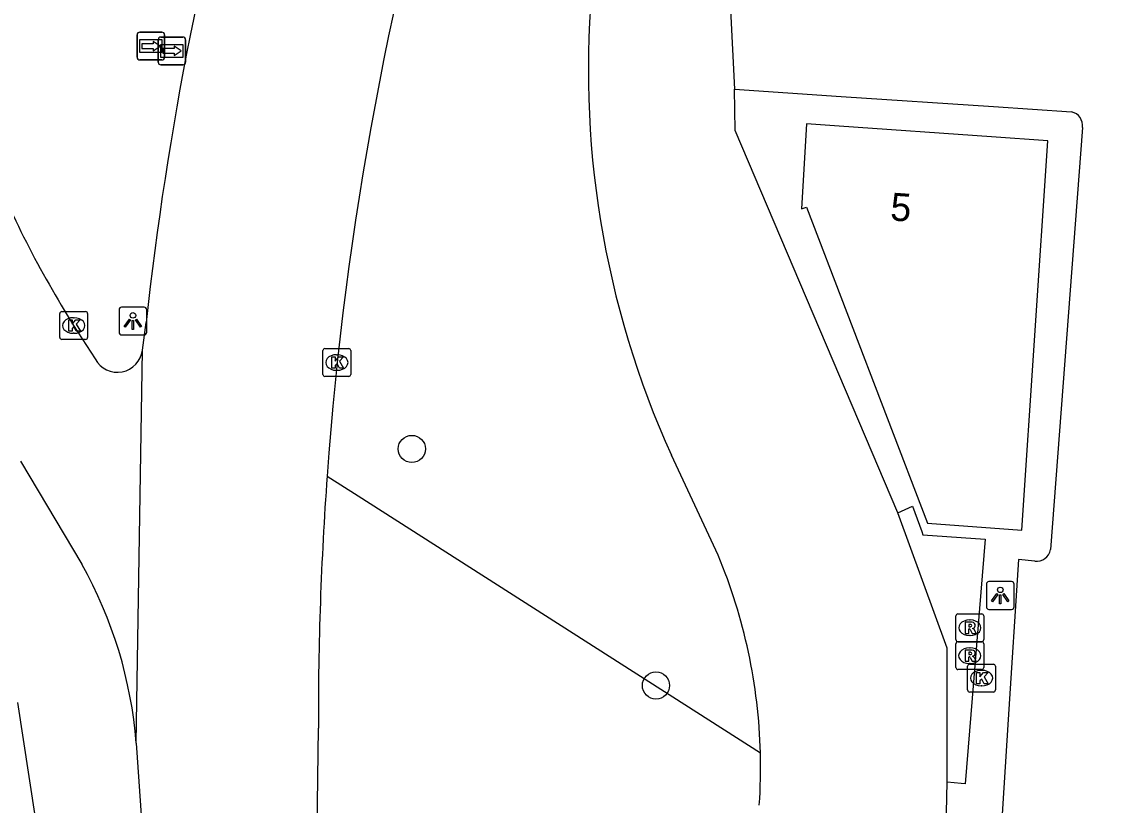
# Model space of a CAD drawing. Extents: x 161084 to 161928, y 385355 to 386522.
# Drawn here: x 161798.81 to 161838.18, y 385406.42 to 385434.56 of the extents above; entities that cross this region are included whole.
import ezdxf

# ---------------------------------------------------------------- set-up
doc = ezdxf.new("R2010")
doc.units = 0
for name, color, linetype in [('IMGEO_Berm_groen', 7, 'Continuous'), ('IMGEO_Boom', 7, 'Continuous'), ('IMGEO_Fietspad_open', 7, 'Continuous'), ('IMGEO_Kolk', 7, 'Continuous'), ('IMGEO_Lichtpunt', 7, 'Continuous'), ('IMGEO_Pand', 7, 'Continuous'), ('IMGEO_Pand_nummerreeks', 7, 'Continuous'), ('IMGEO_Rijbaan_lokaal_gesloten', 7, 'Continuous'), ('IMGEO_Rijbaan_lokaal_open', 7, 'Continuous'), ('IMGEO_Rijbaan_regionaal_gesloten', 7, 'Continuous'), ('IMGEO_Rioolput', 7, 'Continuous'), ('IMGEO_Voetpad_open', 7, 'Continuous'), ('IMGEO_Wegwijzer', 7, 'Continuous')]:
    doc.layers.add(name, color=color, linetype=linetype)

msp = doc.modelspace()

# ---------------------------------------------------------------- linework, layer by layer
at = {"layer": 'IMGEO_Berm_groen'}
for points in [[(161823.838, 385415.395), (161822.158, 385418.993)], [(161809.783, 385418.239), (161810.901, 385417.525), (161825.361, 385408.299)]]:
    msp.add_lwpolyline(points, dxfattribs=at)
for centre, radius, start, end in [((161852.618, 385432.799), 33.443, 174.1577, 204.3823), ((161805.665, 385407.783), 19.702, 1.5001, 22.7269), ((161805.737, 385407.787), 19.63, 356.0062, 1.4938)]:
    msp.add_arc(centre, radius, start, end, dxfattribs=at)
at = {"layer": 'IMGEO_Boom'}
for centre in [(161812.829, 385419.214), (161821.605, 385410.717)]:
    msp.add_circle(centre, 0.489, dxfattribs=at)
at = {"layer": 'IMGEO_Fietspad_open'}
msp.add_lwpolyline([(161798.655, 385410.11), (161800.123, 385400.485), (161800.172, 385400.245)], dxfattribs=at)
at = {"layer": 'IMGEO_Kolk'}
for p, q in [((161800.173, 385423.223), (161800.173, 385424.075)), ((161800.248, 385424.149), (161801.1, 385424.149)), ((161801.174, 385424.075), (161801.174, 385423.223)), ((161800.661, 385423.929), (161800.686, 385423.929)), ((161800.684, 385423.369), (161800.659, 385423.369)), ((161801.1, 385423.149), (161800.248, 385423.149)), ((161809.707, 385422.82), (161810.559, 385422.82)), ((161809.632, 385421.894), (161809.632, 385422.746)), ((161810.12, 385422.6), (161810.145, 385422.6)), ((161810.633, 385422.746), (161810.633, 385421.894)), ((161810.143, 385422.04), (161810.118, 385422.04)), ((161810.559, 385421.82), (161809.707, 385421.82)), ((161832.808, 385410.555), (161832.808, 385411.407)), ((161832.883, 385411.481), (161833.735, 385411.481)), ((161833.809, 385411.407), (161833.809, 385410.555)), ((161833.296, 385411.261), (161833.321, 385411.261)), ((161833.319, 385410.701), (161833.294, 385410.701)), ((161833.735, 385410.481), (161832.883, 385410.481))]:
    msp.add_line(p, q, dxfattribs=at)
for points in [[(161800.173, 385423.223), (161800.173, 385424.075)], [(161800.248, 385424.149), (161801.1, 385424.149)], [(161801.174, 385424.075), (161801.174, 385423.223)], [(161800.494, 385423.849), (161800.617, 385423.849), (161800.617, 385423.698), (161800.747, 385423.849), (161800.911, 385423.849), (161800.765, 385423.698), (161800.918, 385423.449), (161800.766, 385423.449), (161800.681, 385423.613), (161800.617, 385423.546), (161800.617, 385423.449), (161800.494, 385423.449), (161800.494, 385423.849)], [(161801.1, 385423.149), (161800.248, 385423.149)], [(161809.707, 385422.82), (161810.559, 385422.82)], [(161809.632, 385421.894), (161809.632, 385422.746)], [(161809.953, 385422.52), (161810.076, 385422.52), (161810.076, 385422.369), (161810.206, 385422.52), (161810.37, 385422.52), (161810.224, 385422.369), (161810.377, 385422.12), (161810.225, 385422.12), (161810.14, 385422.284), (161810.076, 385422.217), (161810.076, 385422.12), (161809.953, 385422.12), (161809.953, 385422.52)], [(161810.633, 385422.746), (161810.633, 385421.894)], [(161810.559, 385421.82), (161809.707, 385421.82)], [(161832.808, 385410.555), (161832.808, 385411.407)], [(161832.883, 385411.481), (161833.735, 385411.481)], [(161833.809, 385411.407), (161833.809, 385410.555)], [(161833.129, 385411.181), (161833.252, 385411.181), (161833.252, 385411.03), (161833.382, 385411.181), (161833.546, 385411.181), (161833.4, 385411.03), (161833.553, 385410.781), (161833.401, 385410.781), (161833.316, 385410.945), (161833.252, 385410.878), (161833.252, 385410.781), (161833.129, 385410.781), (161833.129, 385411.181)], [(161833.735, 385410.481), (161832.883, 385410.481)]]:
    msp.add_lwpolyline(points, dxfattribs=at)
for centre, start, end in [((161800.25, 385424.073), 91.552, 178.448), ((161800.25, 385424.073), 91.552, 178.448), ((161801.098, 385424.073), 1.552, 88.448), ((161801.098, 385424.073), 1.552, 88.448), ((161800.25, 385423.225), 181.552, 268.448), ((161800.25, 385423.225), 181.552, 268.448), ((161801.098, 385423.225), 271.552, 358.448), ((161801.098, 385423.225), 271.552, 358.448), ((161809.709, 385422.744), 91.552, 178.448), ((161809.709, 385422.744), 91.552, 178.448), ((161810.557, 385422.744), 1.552, 88.448), ((161810.557, 385422.744), 1.552, 88.448), ((161809.709, 385421.896), 181.552, 268.448), ((161809.709, 385421.896), 181.552, 268.448), ((161810.557, 385421.896), 271.552, 358.448), ((161810.557, 385421.896), 271.552, 358.448), ((161832.885, 385411.405), 91.552, 178.448), ((161832.885, 385411.405), 91.552, 178.448), ((161833.733, 385411.405), 1.552, 88.448), ((161833.733, 385411.405), 1.552, 88.448), ((161832.885, 385410.557), 181.552, 268.448), ((161832.885, 385410.557), 181.552, 268.448), ((161833.733, 385410.557), 271.552, 358.448), ((161833.733, 385410.557), 271.552, 358.448)]:
    msp.add_arc(centre, 0.0765, start, end, dxfattribs=at)
for centre, major_axis, ratio, start_param, end_param in [((161800.66, 385423.649), (-0.387, 0.002), 0.722429, 4.712389, 7.853982), ((161800.685, 385423.649), (-0.39, 0.002), 0.717154, 1.570796, 4.712389), ((161810.119, 385422.32), (-0.387, 0.002), 0.722429, 4.712389, 7.853982), ((161810.144, 385422.32), (-0.39, 0.002), 0.717154, 1.570796, 4.712389), ((161833.295, 385410.981), (-0.387, 0.002), 0.722429, 4.712389, 7.853982), ((161833.32, 385410.981), (-0.39, 0.002), 0.717154, 1.570796, 4.712389)]:
    msp.add_ellipse(centre, major_axis=major_axis, ratio=ratio, start_param=start_param, end_param=end_param, dxfattribs=at)
at = {"layer": 'IMGEO_Lichtpunt'}
for p, q in [((161802.303, 385424.214), (161802.303, 385423.407)), ((161802.303, 385424.214), (161802.303, 385423.407)), ((161803.205, 385424.309), (161802.397, 385424.309)), ((161803.205, 385424.309), (161802.397, 385424.309)), ((161803.299, 385423.407), (161803.299, 385424.214)), ((161803.299, 385423.407), (161803.299, 385424.214)), ((161802.397, 385423.313), (161803.205, 385423.313)), ((161802.397, 385423.313), (161803.205, 385423.313)), ((161833.483, 385414.353), (161833.483, 385413.546)), ((161833.483, 385414.353), (161833.483, 385413.546)), ((161834.385, 385414.448), (161833.577, 385414.448)), ((161834.385, 385414.448), (161833.577, 385414.448)), ((161834.479, 385413.546), (161834.479, 385414.353)), ((161834.479, 385413.546), (161834.479, 385414.353)), ((161833.577, 385413.452), (161834.385, 385413.452)), ((161833.577, 385413.452), (161834.385, 385413.452))]:
    msp.add_line(p, q, dxfattribs=at)
for points in [[(161802.677, 385423.878), (161802.716, 385423.85), (161802.528, 385423.588), (161802.49, 385423.615), (161802.677, 385423.878)], [(161802.779, 385423.83), (161802.826, 385423.83), (161802.826, 385423.508), (161802.779, 385423.508), (161802.779, 385423.83)], [(161802.889, 385423.85), (161802.927, 385423.877), (161803.114, 385423.615), (161803.075, 385423.587), (161802.889, 385423.85)], [(161833.857, 385414.017), (161833.896, 385413.989), (161833.708, 385413.727), (161833.67, 385413.754), (161833.857, 385414.017)], [(161833.959, 385413.969), (161834.006, 385413.969), (161834.006, 385413.647), (161833.959, 385413.647), (161833.959, 385413.969)], [(161834.069, 385413.989), (161834.107, 385414.016), (161834.294, 385413.754), (161834.255, 385413.726), (161834.069, 385413.989)]]:
    msp.add_lwpolyline(points, dxfattribs=at)
for centre in [(161802.802, 385424.012), (161833.982, 385414.151)]:
    msp.add_circle(centre, 0.0994, dxfattribs=at)
for centre, start, end in [((161802.397, 385424.214), 90, 180), ((161802.397, 385424.214), 90, 180), ((161803.205, 385424.214), 0, 90), ((161803.205, 385424.214), 0, 90), ((161802.397, 385423.407), 180, 270), ((161802.397, 385423.407), 180, 270), ((161803.205, 385423.407), 270, 0), ((161803.205, 385423.407), 270, 360), ((161833.577, 385414.353), 90, 180), ((161833.577, 385414.353), 90, 180), ((161834.385, 385414.353), 0, 90), ((161834.385, 385414.353), 0, 90), ((161833.577, 385413.546), 180, 270), ((161833.577, 385413.546), 180, 270), ((161834.385, 385413.546), 270, 0), ((161834.385, 385413.546), 270, 360)]:
    msp.add_arc(centre, 0.0946, start, end, dxfattribs=at)
at = {"layer": 'IMGEO_Pand'}
msp.add_lwpolyline([(161828.192, 385430.811), (161827.017, 385430.893), (161826.832, 385427.839), (161827.018, 385427.903), (161831.363, 385416.554), (161834.761, 385416.296), (161835.693, 385430.288), (161833.672, 385430.429), (161828.192, 385430.811)], dxfattribs=at)
at = {"layer": 'IMGEO_Rijbaan_lokaal_gesloten'}
for points in [[(161800.671, 385423.651), (161801.444, 385422.447)], [(161798.757, 385418.779), (161800.964, 385415.071)]]:
    msp.add_lwpolyline(points, dxfattribs=at)
for centre, radius, start, end in [((161833.106, 385444.048), 38.316, 201.8686, 212.1634), ((161802.244, 385422.874), 0.907, 208.1146, 353.2589), ((161787.43, 385407.44), 15.537, 4.4676, 29.4165)]:
    msp.add_arc(centre, radius, start, end, dxfattribs=at)
at = {"layer": 'IMGEO_Rijbaan_lokaal_open'}
for points in [[(161824.225, 385436.183), (161824.424, 385432.14)], [(161824.424, 385432.14), (161828.258, 385431.877), (161833.735, 385431.519), (161836.547, 385431.325)], [(161836.933, 385430.763), (161835.786, 385415.597)], [(161835.223, 385415.179), (161834.635, 385415.241), (161834.264, 385409.491), (161833.579, 385398.725)]]:
    msp.add_lwpolyline(points, dxfattribs=at)
for centre, radius, start, end in [((161836.439, 385430.838), 0.499, 351.412, 77.5531), ((161835.283, 385415.687), 0.511, 263.31, 349.8741), ((161792.28, 385415.181), 47.73, 344.0924, 353.7706)]:
    msp.add_arc(centre, radius, start, end, dxfattribs=at)
at = {"layer": 'IMGEO_Rijbaan_regionaal_gesloten'}
for points in [[(161803.145, 385422.768), (161803.28, 385423.752)], [(161802.92, 385408.65), (161803.145, 385422.768)], [(161809.363, 385401.074), (161809.468, 385409.186)], [(161802.92, 385408.65), (161803.466, 385400.718), (161803.469, 385400.593)]]:
    msp.add_lwpolyline(points, dxfattribs=at)
for centre, radius, start, end in [((161929.841, 385409.507), 120.375, 163.03043, 175.84008), ((161921.548, 385410.938), 118.96, 163.76093, 173.81644), ((161929.866, 385409.529), 120.398, 175.85128, 180.1631)]:
    msp.add_arc(centre, radius, start, end, dxfattribs=at)
at = {"layer": 'IMGEO_Rioolput'}
for p, q in [((161832.387, 385412.364), (161832.387, 385413.216)), ((161832.462, 385413.29), (161833.314, 385413.29)), ((161832.875, 385413.07), (161832.9, 385413.07)), ((161833.388, 385413.216), (161833.388, 385412.364)), ((161832.386, 385411.363), (161832.386, 385412.215)), ((161832.461, 385412.289), (161833.313, 385412.289)), ((161833.314, 385412.29), (161832.462, 385412.29)), ((161832.898, 385412.51), (161832.873, 385412.51)), ((161833.387, 385412.215), (161833.387, 385411.363)), ((161832.874, 385412.069), (161832.899, 385412.069)), ((161832.897, 385411.509), (161832.872, 385411.509)), ((161833.313, 385411.289), (161832.461, 385411.289))]:
    msp.add_line(p, q, dxfattribs=at)
for points in [[(161832.387, 385412.364), (161832.387, 385413.216)], [(161832.462, 385413.29), (161833.314, 385413.29)], [(161832.976, 385412.988), (161832.724, 385412.99), (161832.724, 385412.59)], [(161833.388, 385413.216), (161833.388, 385412.364)], [(161832.724, 385412.59), (161832.848, 385412.59), (161832.848, 385412.752), (161832.859, 385412.752)], [(161832.902, 385412.909), (161832.848, 385412.909), (161832.848, 385412.828)], [(161832.848, 385412.828), (161832.9, 385412.828)], [(161832.906, 385412.723), (161832.977, 385412.59), (161833.117, 385412.59), (161833.052, 385412.716)], [(161832.386, 385411.363), (161832.386, 385412.215)], [(161832.461, 385412.289), (161833.313, 385412.289)], [(161833.314, 385412.29), (161832.462, 385412.29)], [(161833.387, 385412.215), (161833.387, 385411.363)], [(161832.975, 385411.987), (161832.723, 385411.989), (161832.723, 385411.589)], [(161832.901, 385411.908), (161832.847, 385411.908), (161832.847, 385411.827)], [(161832.847, 385411.827), (161832.899, 385411.827)], [(161832.723, 385411.589), (161832.847, 385411.589), (161832.847, 385411.751), (161832.858, 385411.751)], [(161832.905, 385411.722), (161832.976, 385411.589), (161833.116, 385411.589), (161833.051, 385411.715)], [(161833.313, 385411.289), (161832.461, 385411.289)]]:
    msp.add_lwpolyline(points, dxfattribs=at)
for centre, radius, start, end in [((161832.464, 385413.214), 0.0765, 91.552, 178.448), ((161832.464, 385413.214), 0.0765, 91.552, 178.448), ((161832.975, 385412.878), 0.109, 350.3612, 89.416), ((161833.312, 385413.214), 0.0765, 1.552, 88.448), ((161833.312, 385413.214), 0.0765, 1.552, 88.448), ((161832.858, 385412.699), 0.0533, 26.0293, 88.6989), ((161832.884, 385413.017), 0.19, 274.7715, 282.9687), ((161832.908, 385412.813), 0.0964, 77.0061, 93.1865), ((161832.922, 385412.87), 0.0378, 276.6634, 79.6772), ((161832.973, 385412.878), 0.112, 277.5842, 350.9817), ((161832.957, 385412.663), 0.108, 29.5134, 73.7905), ((161832.463, 385412.213), 0.0765, 91.552, 178.448), ((161832.463, 385412.213), 0.0765, 91.552, 178.448), ((161832.464, 385412.366), 0.0765, 181.552, 268.448), ((161832.464, 385412.366), 0.0765, 181.552, 268.448), ((161833.311, 385412.213), 0.0765, 1.552, 88.448), ((161833.311, 385412.213), 0.0765, 1.552, 88.448), ((161833.312, 385412.366), 0.0765, 271.552, 358.448), ((161833.312, 385412.366), 0.0765, 271.552, 358.448), ((161832.883, 385412.016), 0.19, 274.7715, 282.9687), ((161832.907, 385411.812), 0.0964, 77.0061, 93.1865), ((161832.921, 385411.869), 0.0378, 276.6634, 79.6772), ((161832.974, 385411.877), 0.109, 350.3612, 89.416), ((161832.972, 385411.877), 0.112, 277.5842, 350.9817), ((161832.857, 385411.698), 0.0533, 26.0293, 88.6989), ((161832.956, 385411.662), 0.108, 29.5134, 73.7905), ((161832.463, 385411.365), 0.0765, 181.552, 268.448), ((161832.463, 385411.365), 0.0765, 181.552, 268.448), ((161833.311, 385411.365), 0.0765, 271.552, 358.448), ((161833.311, 385411.365), 0.0765, 271.552, 358.448)]:
    msp.add_arc(centre, radius, start, end, dxfattribs=at)
for centre, major_axis, ratio, start_param, end_param in [((161832.874, 385412.79), (-0.387, 0.002), 0.722429, 4.712389, 7.853982), ((161832.899, 385412.79), (-0.39, 0.002), 0.717154, 1.570796, 4.712389), ((161832.873, 385411.789), (-0.387, 0.002), 0.722429, 4.712389, 7.853982), ((161832.898, 385411.789), (-0.39, 0.002), 0.717154, 1.570796, 4.712389)]:
    msp.add_ellipse(centre, major_axis=major_axis, ratio=ratio, start_param=start_param, end_param=end_param, dxfattribs=at)
at = {"layer": 'IMGEO_Voetpad_open'}
for points in [[(161830.301, 385416.92), (161824.454, 385430.65), (161824.424, 385432.14)], [(161830.301, 385416.92), (161830.824, 385417.156), (161831.159, 385416.247), (161831.199, 385416.131), (161833.438, 385415.97), (161832.726, 385407.187), (161832.573, 385407.2), (161832.079, 385407.241)], [(161832.079, 385407.241), (161832.079, 385412.061), (161830.301, 385416.92)], [(161831.815, 385398.932), (161831.934, 385400.658), (161832.079, 385407.241)]]:
    msp.add_lwpolyline(points, dxfattribs=at)
at = {"layer": 'IMGEO_Wegwijzer'}
for p, q in [((161802.952, 385433.288), (161802.952, 385434.088)), ((161802.952, 385434.088), (161802.952, 385433.288)), ((161803.052, 385434.188), (161803.842, 385434.188)), ((161803.842, 385434.188), (161803.052, 385434.188)), ((161803.708, 385433.113), (161803.708, 385433.913)), ((161803.708, 385433.913), (161803.708, 385433.113)), ((161803.808, 385434.013), (161804.598, 385434.013)), ((161804.598, 385434.013), (161803.808, 385434.013)), ((161803.942, 385434.088), (161803.942, 385433.288)), ((161803.942, 385433.288), (161803.942, 385434.088)), ((161804.698, 385433.913), (161804.698, 385433.113)), ((161804.698, 385433.113), (161804.698, 385433.913)), ((161803.842, 385433.188), (161803.052, 385433.188)), ((161803.052, 385433.188), (161803.842, 385433.188)), ((161804.598, 385433.013), (161803.808, 385433.013)), ((161803.808, 385433.013), (161804.598, 385433.013))]:
    msp.add_line(p, q, dxfattribs=at)
for points in [[(161803.053, 385433.92), (161803.841, 385433.92), (161803.841, 385433.456), (161803.053, 385433.456), (161803.053, 385433.92)], [(161803.118, 385433.772), (161803.118, 385433.688), (161803.118, 385433.604), (161803.529, 385433.604), (161803.529, 385433.521), (161803.776, 385433.688), (161803.529, 385433.855), (161803.529, 385433.772), (161803.118, 385433.772)], [(161803.809, 385433.745), (161804.597, 385433.745), (161804.597, 385433.281), (161803.809, 385433.281), (161803.809, 385433.745)], [(161803.874, 385433.597), (161803.874, 385433.513), (161803.874, 385433.429), (161804.285, 385433.429), (161804.285, 385433.346), (161804.532, 385433.513), (161804.285, 385433.68), (161804.285, 385433.597), (161803.874, 385433.597)]]:
    msp.add_lwpolyline(points, dxfattribs=at)
for centre, start, end in [((161803.052, 385434.088), 90, 180), ((161803.052, 385434.088), 90, 180), ((161803.808, 385433.913), 90, 180), ((161803.808, 385433.913), 90, 180), ((161803.842, 385434.088), 0, 90), ((161803.842, 385434.088), 360, 90), ((161804.598, 385433.913), 0, 90), ((161804.598, 385433.913), 360, 90), ((161803.052, 385433.288), 180, 270), ((161803.052, 385433.288), 180, 270), ((161803.808, 385433.113), 180, 270), ((161803.808, 385433.113), 180, 270), ((161803.842, 385433.288), 270, 0), ((161803.842, 385433.288), 270, 0), ((161804.598, 385433.113), 270, 0), ((161804.598, 385433.113), 270, 0)]:
    msp.add_arc(centre, 0.1, start, end, dxfattribs=at)

# ---------------------------------------------------------------- texts
at = {"layer": 'IMGEO_Pand_nummerreeks'}
msp.add_text('5', height=1, rotation=356.0611, dxfattribs=at).set_placement((161830.008, 385427.428))

doc.saveas('drawing.dxf')
